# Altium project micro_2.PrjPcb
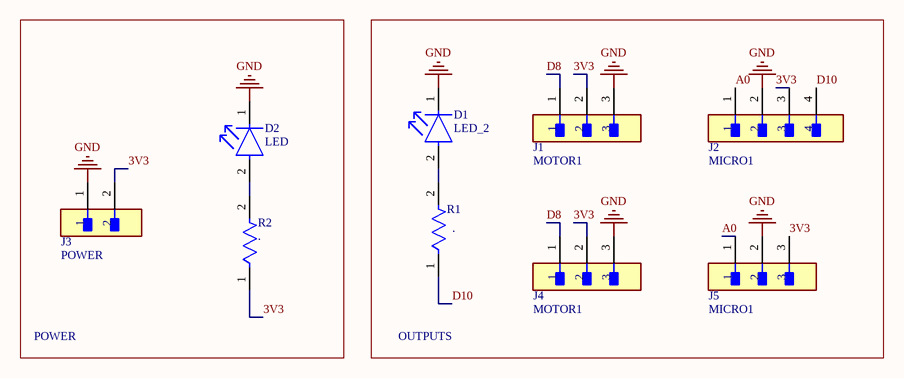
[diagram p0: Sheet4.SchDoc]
1 sheet, 9 parts. Net scope: global (net labels, ports and power ports of the same name join across sheets).
Board file: PCB7.PcbDoc

## Sheet Sheet4.SchDoc
size A4; SheetNumber: 1; SheetTotal: 1

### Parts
D1  LED_2  [FP-LTST-C150KSKT-MFG]
D2  LED  [FP-LTST-C150KSKT-MFG]
J1  MOTOR1  [FP-PR20203VBNN-MFG]
J2  MICRO1  [FP-TSW-104-22-G-S-MFG]
J3  POWER  [FP-TMM-102-01-L-S-MFG]
J4  MOTOR1  [FP-PR20203VBNN-MFG]
J5  MICRO1  [FP-PR20203VBNN-MFG]
R1  .  [FP-AC1206-MFG]
R2  .  [FP-AC1206-MFG]

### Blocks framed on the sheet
POWER: D2 J3 R2
OUTPUTS: D1 J1 J2 J4 J5 R1

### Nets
GND: D1.1(C) D2.1(C) J1.3 J2.2 J3.1 J4.3 J5.2
3V3: J1.2 J2.3 J3.2 J4.2 J5.3 R2.1
A0: J2.1 J5.1
D8: J1.1 J4.1
D10: J2.4 R1.1
NetD1_2: D1.2(A) R1.2
NetD2_2: D2.2(A) R2.2

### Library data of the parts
D1 D2 = CMP-2000-06618-2: LED YELLOW CLEAR 1206 SMD; Power Rating: 75mW; Wavelength: 588nm; Forward Current: 30mA; Test Current: 20mA; Viewing Angle: 130°; Forward Voltage: 2.4V; Luminous Intensity: 60mcd; Lens Style: Diffused; Number of Elements: 1; Reverse Voltage: 5V; Lens Color: Colorless; Dominant Wavelength: 587nm
J1 J4 J5 = CMP-77940-000002-1: CONN HEADER VERT 3POS 2.54MM; Manufacturer Part Number: PR20203VBNN; Manufacturer: Metz Connect; Conn Orientation: Straight; Current Rating: 3A; Number Of Contacts: 3; Conn Gender: Male
J2 = CMP-02766-001236-1: CONN HEADER VERT 4POS 2.54MM; Number of Contacts: 4; Gender: Male
J3 = CMP-02766-001606-1: CONN HEADER VERT 2POS 2MM; Number of Positions: 2; Gender: Male; Max Current Rating: 3.9A; Max Voltage Rating (AC): 500V
R1 R2 = CMP-03412-032679-1: RES SMD 2.21K OHM 1% 1/4W 1206; Manufacturer: Yageo; Manufacturer Part Number: AC1206FR-072K21L; Automotive Grade: Grade 0; Voltage Rating: 200V; Tolerance: 0.01; Value: 2.21KΩ; Power Rating: 0.25W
